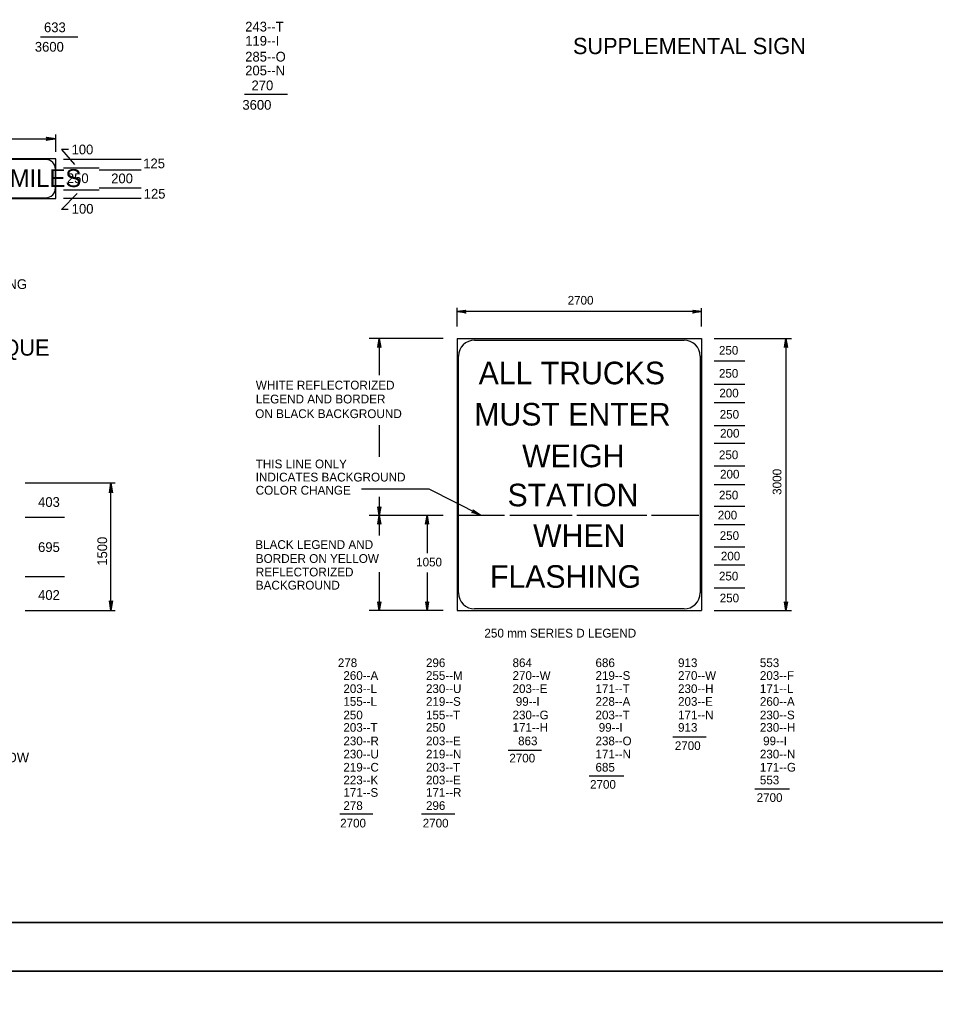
# Model space of a CAD drawing. Extents: x 649604 to 650509, y 298458 to 299646.
# Drawn here: x 649924.8 to 650206.9, y 299044.1 to 299344.6 of the extents above; entities that cross this region are included whole.
import ezdxf

# ---------------------------------------------------------------- set-up
doc = ezdxf.new("R2010")
doc.units = 0
for name, color, linetype in [('1', 7, 'Continuous'), ('2', 7, 'Continuous'), ('3', 7, 'Continuous'), ('PLT-BNDY', 7, 'Continuous')]:
    doc.layers.add(name, color=color, linetype=linetype)

# ---------------------------------------------------------------- blocks, each defined once
blk = doc.blocks.new('RARROW')
at = {"layer": '3'}
blk.add_lwpolyline([(-2.2695, 0.285), (-2.184875, 0.12075), (0, 0), (-2.2695, 0.285), (-2.38575, 0.384625), (0, 0), (-2.183125, -0.108), (-2.262875, -0.2705), (0, 0), (-2.38575, -0.379125), (-2.262875, -0.2705)], dxfattribs=at)

msp = doc.modelspace()

# ---------------------------------------------------------------- linework, layer by layer
at = {"layer": '1'}
for p, q in [((650430.31, 299066.63), (649644.31, 299066.63)), ((649644.31, 299066.63), (650230.31, 299066.63))]:
    msp.add_line(p, q, dxfattribs=at)
at = {"layer": '2'}
for p, q in [((649931.26, 299339.35), (649942.76, 299339.35)), ((649994.04, 299321.6), (650007.29, 299321.6)), ((649936.02, 299303.88), (649936.02, 299309.27)), ((649848.15, 299307.89), (649936.02, 299307.89)), ((649936.02, 299301.78), (649848.15, 299301.78)), ((649936.02, 299289.5), (649936.02, 299301.78)), ((649938.4, 299301.68), (649962.25, 299301.68)), ((649938.4, 299299.01), (649949.33, 299299.01)), ((649949.33, 299298.35), (649962.32, 299298.35)), ((649938.4, 299292.18), (649949.33, 299292.18)), ((649949.33, 299292.85), (649962.32, 299292.85)), ((649848.15, 299289.5), (649936.02, 299289.5)), ((649938.4, 299289.6), (649962.25, 299289.6)), ((650059.55, 299250.15), (650059.55, 299255.83)), ((650134.82, 299250.15), (650134.82, 299255.72)), ((650134.82, 299254.71), (650059.55, 299254.71)), ((650055.23, 299246.38), (650032.48, 299246.38)), ((650035.59, 299246.38), (650035.59, 299235.13)), ((650059.55, 299246.38), (650134.82, 299246.38)), ((650059.55, 299246.38), (650059.55, 299162.68)), ((650134.82, 299246.38), (650134.82, 299162.68)), ((650138.72, 299246.38), (650162.49, 299246.38)), ((650160.8, 299246.38), (650160.8, 299162.68)), ((650064.95, 299245.93), (650129.42, 299245.93)), ((650060, 299168.08), (650060, 299240.98)), ((650134.37, 299240.98), (650134.37, 299168.08)), ((650138.72, 299239.52), (650148.1, 299239.52)), ((650138.72, 299232.32), (650148.1, 299232.32)), ((650138.72, 299226.69), (650148.1, 299226.69)), ((650035.59, 299219.76), (650035.59, 299209.95)), ((650138.72, 299219.61), (650148.1, 299219.61)), ((650138.72, 299214.21), (650148.1, 299214.21)), ((650138.72, 299207.23), (650148.1, 299207.23)), ((649926.6, 299201.93), (649954.23, 299201.93)), ((649952.98, 299162.68), (649952.98, 299201.93)), ((650138.72, 299201.49), (650148.1, 299201.49)), ((650051, 299200.03), (650030.1, 299200.03)), ((650066.75, 299192.04), (650051, 299200.03)), ((650035.59, 299197.65), (650035.59, 299191.93)), ((650055.23, 299191.93), (650032.48, 299191.93)), ((650035.59, 299191.93), (650035.59, 299185.74)), ((650050.32, 299191.93), (650050.32, 299180.34)), ((650074.18, 299191.93), (650060.23, 299191.93)), ((650094.99, 299191.93), (650075.75, 299191.93)), ((650117.94, 299191.93), (650096.45, 299191.93)), ((650134.03, 299191.93), (650119.4, 299191.93)), ((650138.72, 299194.74), (650148.1, 299194.74)), ((649926.6, 299191.43), (649938.66, 299191.43)), ((650138.72, 299189.12), (650148.1, 299189.12)), ((650138.72, 299182.26), (650148.1, 299182.26)), ((650035.59, 299174.49), (650035.59, 299162.68)), ((650050.32, 299174.38), (650050.32, 299162.68)), ((650138.72, 299176.74), (650148.1, 299176.74)), ((649926.6, 299173.18), (649938.66, 299173.18)), ((650138.72, 299169.66), (650148.1, 299169.66)), ((649926.6, 299162.68), (649954.23, 299162.68)), ((650055.23, 299162.68), (650032.48, 299162.68)), ((650059.55, 299162.68), (650134.82, 299162.68)), ((650129.42, 299163.13), (650064.95, 299163.13)), ((650138.72, 299162.68), (650162.49, 299162.68)), ((650125.93, 299123.76), (650136.28, 299123.76)), ((650075.3, 299119.71), (650085.54, 299119.71)), ((650100.17, 299111.72), (650110.85, 299111.72)), ((650151.24, 299107.78), (650161.93, 299107.78)), ((650023.44, 299100.02), (650033.57, 299100.02)), ((650048.64, 299100.02), (650058.88, 299100.02))]:
    msp.add_line(p, q, dxfattribs=at)
for points in [[(649939.94, 299304.57), (649937.75, 299304.57), (649941.78, 299300.04)], [(649932.9, 299301.53), (649851.4, 299301.53)], [(649935.9, 299292.75), (649935.9, 299298.53)], [(649939.84, 299286.15), (649937.7, 299286.15), (649942.52, 299291.03)], [(649851.4, 299289.75), (649932.9, 299289.75)]]:
    msp.add_lwpolyline(points, dxfattribs=at)
for centre, radius, start, end in [((649932.9, 299298.53), 3, 0, 90), ((649932.9, 299292.75), 3, 270, 0), ((650064.95, 299240.98), 4.95, 90, 180), ((650129.42, 299240.98), 4.95, 0, 90), ((650064.95, 299168.08), 4.95, 180, 270), ((650129.42, 299168.08), 4.95, 270, 0)]:
    msp.add_arc(centre, radius, start, end, dxfattribs=at)
at = {"layer": 'PLT-BNDY'}
for points in [[(649604.31, 299645.63), (650445.31, 299645.63), (650445.31, 299051.63), (649604.31, 299051.63)], [(649604.31, 299051.63), (650445.31, 299051.63), (650445.31, 298457.63), (649604.31, 298457.63)]]:
    msp.add_lwpolyline(points, close=True, dxfattribs=at)

# ---------------------------------------------------------------- block references
at = {"layer": '2'}
for p, xscale, yscale in [((649936.02, 299307.89), 1.2574347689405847, 1.3092961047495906), ((650134.82, 299254.71), 1.1316912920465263, 1.1783664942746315)]:
    msp.add_blockref('RARROW', p, dxfattribs=dict(at, xscale=xscale, yscale=yscale))
for p, xscale, yscale, rotation in [((650059.55, 299254.71), 1.1316912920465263, 1.1783664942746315, 180), ((650035.59, 299246.38), 1.1316912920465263, 1.1783664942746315, 89.99999999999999), ((650160.8, 299246.38), 1.1316912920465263, 1.1783664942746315, 89.99999999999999), ((649952.98, 299201.93), 1.2574347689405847, 1.3092961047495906, 89.99999999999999), ((650035.59, 299191.93), 1.1316912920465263, 1.1783664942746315, -90.00000000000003), ((650035.59, 299191.93), 1.1316912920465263, 1.1783664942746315, 89.99999999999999), ((650050.32, 299191.93), 1.1316912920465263, 1.1783664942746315, 89.99999999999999), ((650066.75, 299192.04), 1.131691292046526, 1.1783664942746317, -26.73304276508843), ((649952.98, 299162.68), 1.2574347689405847, 1.3092961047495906, -90.00000000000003), ((650035.59, 299162.68), 1.1316912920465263, 1.1783664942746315, -90.00000000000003), ((650050.32, 299162.68), 1.1316912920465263, 1.1783664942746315, -90.00000000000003), ((650160.8, 299162.68), 1.1316912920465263, 1.1783664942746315, -90.00000000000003)]:
    msp.add_blockref('RARROW', p, dxfattribs=dict(at, xscale=xscale, yscale=yscale, rotation=rotation))

# ---------------------------------------------------------------- texts
for s, height, p in [('633', 3, (649932.35, 299340.73)), (' 243--T', 3, (649993.19, 299340.94)), (' 119--I', 3, (649993.2, 299336.57)), ('3600', 3, (649929.53, 299334.73)), ('SUPPLEMENTAL SIGN', 5, (650095.23, 299333.98)), (' 285--O', 3, (649993.19, 299331.69)), (' 205--N', 3, (649993.19, 299327.44)), ('270', 3, (649996.25, 299322.85)), ('3600', 3, (649993.44, 299316.85)), ('100', 3, (649940.84, 299303.12)), ('125', 3, (649962.91, 299298.83)), ('NEXT REST AREA    MILES', 5.5, (649850.25, 299293.05)), ('250', 3, (649939.4, 299294.26)), ('200', 3, (649953.04, 299294.21)), ('125', 3, (649963.06, 299289.49)), ('100', 3, (649940.89, 299284.85)), ('30% REDUCED SPACING', 3, (649878.97, 299261.65)), ('2700', 2.67, (650093.6, 299256.85)), ('SUPPLEMENTAL PLAQUE', 5, (649851.56, 299241.14)), ('250', 2.67, (650140.18, 299241.44)), ('ALL TRUCKS', 6.955, (650066.19, 299232.32)), ('250', 2.67, (650140.18, 299234.34)), ('WHITE REFLECTORIZED', 2.7, (649997.57, 299230.71)), ('200', 2.67, (650140.3, 299228.28)), ('LEGEND AND BORDER', 2.7, (649997.57, 299226.42)), ('MUST ENTER', 6.955, (650064.84, 299219.61)), ('ON BLACK BACKGROUND', 2.7, (649997.39, 299221.91)), ('250', 2.67, (650140.42, 299221.73)), ('200', 2.67, (650140.53, 299215.9)), ('WEIGH', 6.955, (650079.58, 299206.78)), ('250', 2.67, (650140.18, 299209.26)), ('THIS LINE ONLY', 2.7, (649997.53, 299206.44)), ('INDICATES BACKGROUND', 2.7, (649997.53, 299202.39)), ('200', 2.67, (650140.53, 299203.3)), ('COLOR CHANGE', 2.7, (649997.53, 299198.34)), ('STATION', 6.955, (650075.08, 299194.74)), ('250', 2.67, (650140.18, 299196.87)), ('403', 3, (649930.53, 299194.56)), ('200', 2.67, (650139.83, 299190.7)), ('WHEN', 6.955, (650082.95, 299182.26)), ('250', 2.67, (650140.42, 299184.39)), ('695', 3, (649930.53, 299180.68)), ('BLACK LEGEND AND', 2.7, (649997.39, 299181.61)), ('BORDER ON YELLOW', 2.7, (649997.56, 299177.32)), ('200', 2.67, (650140.77, 299178.09)), ('1050', 2.67, (650046.95, 299176.24)), ('REFLECTORIZED ', 2.7, (649997.56, 299173.16)), ('FLASHING', 6.955, (650069.68, 299169.66)), ('250', 2.67, (650140.18, 299171.92)), ('BACKGROUND', 2.7, (649997.56, 299169.11)), ('402', 3, (649930.53, 299165.93)), ('250', 2.67, (650140.42, 299165.17)), ('250 mm SERIES D LEGEND', 2.7, (650067.95, 299154.34)), ('  278    ', 2.67, (650020.85, 299145.24)), (' 296   ', 2.67, (650048.98, 299145.24)), (' 864   ', 2.67, (650075.64, 299145.24)), (' 686   ', 2.67, (650101.18, 299145.24)), (' 913   ', 2.67, (650126.6, 299145.24)), (' 553   ', 2.67, (650151.8, 299145.24)), (' 260--A', 2.67, (650023.55, 299141.31)), (' 255--M', 2.67, (650048.98, 299141.31)), (' 270--W', 2.67, (650075.64, 299141.31)), (' 219--S', 2.67, (650101.18, 299141.31)), (' 270--W', 2.67, (650126.6, 299141.31)), (' 203--F', 2.67, (650151.8, 299141.31)), (' 203--L', 2.67, (650023.55, 299137.26)), (' 230--U', 2.67, (650048.98, 299137.26)), (' 203--E', 2.67, (650075.64, 299137.26)), (' 171--T', 2.67, (650101.18, 299137.26)), (' 230--H', 2.67, (650126.6, 299137.26)), (' 171--L', 2.67, (650151.8, 299137.26)), (' 155--L', 2.67, (650023.55, 299133.32)), (' 219--S', 2.67, (650048.98, 299133.32)), ('  99--I', 2.67, (650075.64, 299133.32)), (' 228--A', 2.67, (650101.18, 299133.32)), (' 203--E', 2.67, (650126.6, 299133.32)), (' 260--A', 2.67, (650151.8, 299133.32)), (' 250   ', 2.67, (650023.55, 299129.16)), (' 155--T', 2.67, (650048.98, 299129.16)), (' 230--G', 2.67, (650075.64, 299129.16)), (' 203--T', 2.67, (650101.18, 299129.16)), (' 171--N', 2.67, (650126.6, 299129.16)), (' 230--S', 2.67, (650151.8, 299129.16)), (' 203--T', 2.67, (650023.55, 299125.33)), (' 250   ', 2.67, (650048.98, 299125.33)), (' 171--H', 2.67, (650075.64, 299125.33)), ('  99--I', 2.67, (650101.18, 299125.33)), (' 913   ', 2.67, (650126.6, 299125.33)), (' 230--H', 2.67, (650151.8, 299125.33)), (' 230--R', 2.67, (650023.55, 299121.17)), (' 203--E', 2.67, (650048.98, 299121.17)), ('863   ', 2.67, (650078.34, 299121.17)), (' 238--O', 2.67, (650101.18, 299121.17)), ('  99--I', 2.67, (650151.8, 299121.17)), (' 230--U', 2.67, (650023.55, 299117.12)), (' 219--N', 2.67, (650048.98, 299117.12)), (' 171--N', 2.67, (650101.18, 299117.12)), ('2700   ', 2.67, (650126.6, 299119.71)), (' 230--N', 2.67, (650151.8, 299117.12)), (' 695--ARROW', 3, (649901.9, 299115.9)), ('2700   ', 2.67, (650075.64, 299115.88)), (' 219--C', 2.67, (650023.55, 299113.07)), (' 203--T', 2.67, (650048.98, 299113.07)), (' 685   ', 2.67, (650101.18, 299113.07)), (' 171--G', 2.67, (650151.8, 299113.07)), (' 223--K', 2.67, (650023.55, 299109.13)), (' 203--E', 2.67, (650048.98, 299109.13)), (' 553   ', 2.67, (650151.8, 299109.13)), (' 171--S', 2.67, (650023.55, 299105.31)), (' 171--R', 2.67, (650048.98, 299105.31)), ('2700 ', 2.67, (650100.5, 299107.78)), ('2700   ', 2.67, (650151.8, 299103.73)), (' 278   ', 2.67, (650023.55, 299101.26)), (' 296   ', 2.67, (650048.98, 299101.26)), ('2700   ', 2.67, (650023.55, 299095.86)), ('2700   ', 2.67, (650048.98, 299095.86))]:
    msp.add_text(s, height=height, dxfattribs=at).set_placement(p)
for s, height, p in [('3000', 2.7, (650159.41, 299198.26)), ('1500', 3, (649951.79, 299176.45))]:
    msp.add_text(s, height=height, rotation=90, dxfattribs=at).set_placement(p)

doc.saveas('drawing.dxf')
